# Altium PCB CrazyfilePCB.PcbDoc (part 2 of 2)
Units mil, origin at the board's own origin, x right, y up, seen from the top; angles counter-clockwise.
Board outline 3667.19 x 3670.52 mil, 4 copper layers (Top Layer, GND, VCC, Bottom Layer); 99 components, 96 nets, 358 pads, 80 vias.
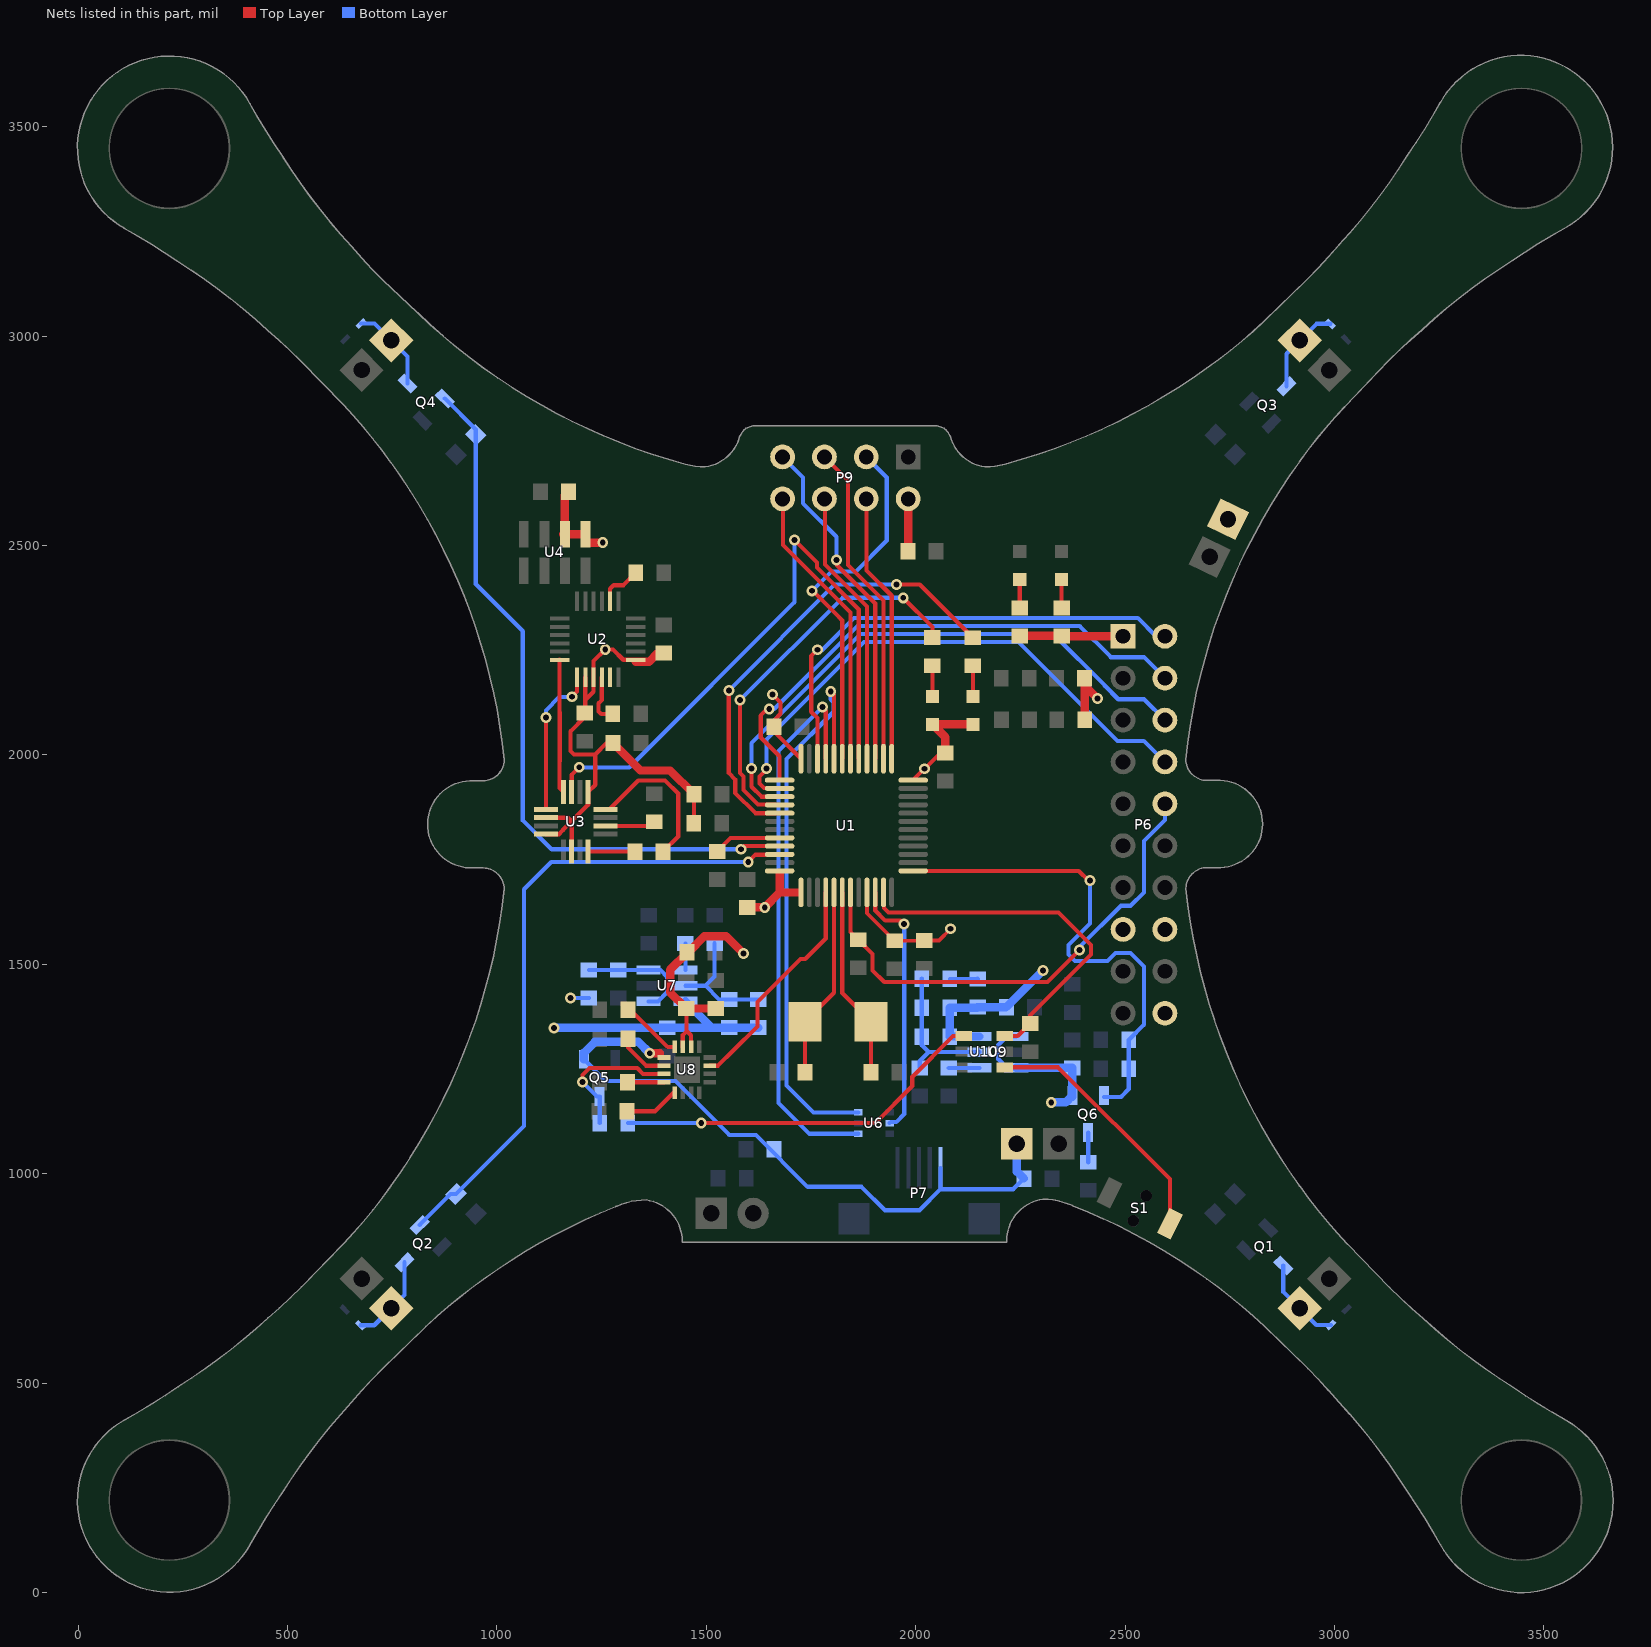
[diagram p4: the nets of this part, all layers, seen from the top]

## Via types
v1: diameter 25.98, hole 14, Top Layer to Bottom Layer, tented both sides, 77 vias
v2: diameter 152.84, hole 113.47, Top Layer to Bottom Layer, 2 vias
v3: diameter 25.98, hole 12.99, Top Layer to Bottom Layer, tented top, 1 vias

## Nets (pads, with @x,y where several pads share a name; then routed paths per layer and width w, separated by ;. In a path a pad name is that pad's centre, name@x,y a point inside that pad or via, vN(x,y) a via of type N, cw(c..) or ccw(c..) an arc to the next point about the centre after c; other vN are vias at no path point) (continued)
MOTOR3: Q2.2 R7.2 U1.46 | length 1556.2
  Top Layer w10: v1(1600.39,1744.09) 1617.97,1761.67 U1.46@1674.49,1761.67
  Bottom Layer w10: Q2.2@815.73,877.51 889.51,951.29 R7.2@902.47,951.29 1064.96,1113.78 1064.96,1679.13 1129.92,1744.09 v1(1600.39,1744.09)
MOTOR4: Q4.2 R9.2 U1.45 | length 1729.4
  Top Layer w10: v1(1582.68,1774.61) 1590.11,1782.04 U1.45@1675.17,1782.04
  Bottom Layer w10: Q4.2@875.81,2850.97 949.65,2777.13 R9.2@949.65,2764.44 949.65,2407.63 1062.01,2295.28 1062.01,1843.5 1130.91,1774.61 v1(1582.68,1774.61)
NetC1_2: C1.2 U1.5 Y1.1 | length 458.4
  Top Layer w10: C1.2@1735.93,1242.08 Y1.1@1735.93,1362.83 1805.09,1431.99 U1.5@1805.09,1671.81
NetC2_2: C2.2 U1.6 Y1.2 | length 555.5
  Top Layer w10: U1.6@1824.78,1671.81 1824.78,1431.35 ; C2.2@1893.36,1241.73 Y1.2@1893.41,1362.83 ; 1824.78,1431.35 Y1.2@1893.41,1362.83 ; 1824.78,1431.35 Y1.2@1893.41,1362.83
NetC3_1: 
NetC9_1: C9.1 U3.12 | length 368.2
  Top Layer w10: U3.12@1259.8,1869.58 1268.47,1869.58 1337.67,1938.78 1401.66,1938.78 1433.07,1907.37 1433.07,1805.16 C9.1@1396.94,1769.03
NetC9_2: C9.2 U3.8 | length 111.9
  Top Layer w10: U3.8@1218.07,1769.03 C9.2@1330.01,1769.03
NetC11_2: C11.2 U3.10 | length 120.5
  Top Layer w10: U3.10@1259.8,1830.21 1366.26,1830.21 C11.2@1376.18,1840.13
NetC13_2: C13.2 U2.10 | length 121
  Top Layer w10: U2.10@1250.66,2185.46 1250.66,2130.7 1243.05,2123.09 1243.05,2103.83 1249.17,2097.71 C13.2@1276.7,2097.71
NetC14_2: C14.2 U2.20 | length 106.8
  Top Layer w10: U2.20@1270.35,2366.88 1270.51,2367.04 1270.51,2396.59 1279.12,2405.2 1302.11,2405.2 C14.2@1331.73,2434.82
NetC28_2: C28.2 R22.1 U7.1 U7.3 | length 283.6
  Bottom Layer w10: R22.1@1220.06,1486.22 U7.3@1362.37,1486.22 1390.52,1486.22 1406.88,1469.86 1406.88,1433.52 1384.77,1411.42 U7.1@1362.37,1411.42
NetC30_2: C30.2 U7.4 | length 63.8
  Bottom Layer w10: C30.2@1450.18,1549.91 1450.18,1486.41 U7.4@1450.37,1486.22
NetC31_1: C31.1 R24.2 R25.1 U7.5 | length 298.1
  Bottom Layer w10: U7.5@1450.37,1448.82 1497.8,1448.82 ; R24.2@1520,1549.95 1520,1471.02 1497.8,1448.82 ; R25.1@1624.4,1415.73 C31.1@1555.12,1415.73 1530.89,1415.73 1497.8,1448.82
NetC33_2: C33.2 U9.4 | length 72.9
  Bottom Layer w10: C33.2@2079.3,1252.6 U9.4@2152.22,1252.6
NetC34_1: C34.1 R27.2 R28.1 R29.1 U9.5 | length 419.3
  Bottom Layer w10: R27.2@2009.9,1252.2 2009.9,1268.57 2031.42,1290.09 ; R28.1@2014.51,1396.74 R29.1@2014.51,1465.84 ; U9.5@2152.31,1290.09 2031.42,1290.09 ; C34.1@2014.73,1327.43 2014.73,1306.77 2031.42,1290.09 ; C34.1@2014.73,1327.43 R28.1@2014.71,1396.54 C34.1@2014.73,1327.43
NetC36_2: C36.2 Q6.2 R35.2 U1.13 | length 1213.1
  Top Layer w10: U1.13@1994.07,1722.99 2389.49,1722.99 2412.68,1699.8 v1(2416.34,1699.8)
  Bottom Layer w10: v1(2416.34,1699.8) 2416.34,1597.23 2364.74,1545.63 2364.74,1523.27 2380.55,1507.46 2458.09,1507.46 2477.26,1526.63 2513.32,1526.63 2545.28,1494.67 2545.28,1355.67 C36.2@2508.83,1319.23 R35.2@2508.83,1249.93 2508.83,1201.75 2490.47,1183.38 ; Q6.2@2450.06,1183.07 2491.14,1183.07
NetD1_2: D1.2 R4.2 | length 73.2
  Top Layer w10: D1.2@2136.81,2139.42 R4.2@2136.81,2212.6
NetD2_2: D2.2 R5.2 | length 73.3
  Top Layer w10: D2.2@2040.19,2139.67 R5.2@2040.19,2212.95
NetD3_1: D3.1 R31.1 | length 68.4
  Top Layer w10: R31.1@2348.23,2350.59 D3.1@2348.23,2419.03
NetD4_1: D4.1 R32.1 | length 67.9
  Top Layer w10: R32.1@2248.58,2351.01 D4.1@2248.58,2418.89
NetH1_1: H1.1 P1.1 Q1.1 | length 209.5
  Bottom Layer w10: Q1.1@2878.01,780.88 2878.01,717.46 P1.1@2917.09,678.39 2956.64,638.83 H1.1@2991.53,638.83
NetH2_1: H2.1 P2.2 Q2.1 | length 213.3
  Bottom Layer w10: H2.1@674.27,637.93 707.13,637.93 P2.2@747.9,678.7 779.68,710.48 Q2.1@779.68,788.29
NetH3_1: H3.1 P3.2 Q3.1 | length 212.1
  Bottom Layer w10: Q3.1@2885.72,2880.01 2885.72,2957.92 P3.2@2917.4,2989.6 2957.07,3029.27 H3.1@2990.33,3029.27
NetH4_1: H4.1 P4.1 Q4.1 | length 207.6
  Bottom Layer w10: H4.1@675.57,3029.87 707.65,3029.87 P4.1@747.81,2989.71 786.59,2950.94 Q4.1@786.59,2887.02
NetP9_3: 
NetP9_4: 
NetP9_5: 
NetP9_6: 
NetP9_7: 
NetP9_8: 
NetQ5_3: Q5.3 R20.2 U8.15 | length 342.6
  Top Layer w10: v1(1204.72,1218.5) 1204.72,1235.68 1221.25,1252.2 1335.21,1252.2 1349.33,1238.09 U8.15@1399.21,1238.09
  Bottom Layer w10: v1(1204.72,1218.5) 1238.7,1184.53 Q5.3@1245.27,1184.53 ; R20.2@1245.54,1120.64 Q5.3@1245.54,1184.26
NetQ6_3: Q6.3 R33.1 | length 70.4
  Bottom Layer w10: R33.1@2411.98,1027.34 Q6.3@2411.98,1097.75
NetR1_2: R1.2 U1.44 | length 162.6
  Top Layer w10: R1.2@1525.92,1769.48 1558.17,1801.73 U1.44@1675.17,1801.73
NetR4_1: R4.1 U1.41 | length 1117.3
  Top Layer w10: v1(1553.96,2153.92) 1553.96,1956.46 1569.08,1941.34 1569.08,1909.02 1617.32,1860.78 U1.41@1675.17,1860.78 ; v1(1954.72,2406.5) 2009.84,2406.5 R4.1@2136.81,2279.53
  Bottom Layer w10: v1(1553.96,2153.92) 1806.53,2406.5 v1(1954.72,2406.5)
NetR5_1: R5.1 U1.40 | length 933.8
  Top Layer w10: v1(1580.95,2130.93) 1580.95,1956.34 1588.94,1948.35 1588.94,1916.03 1623.82,1881.15 1674.49,1881.15 U1.40@1675.17,1880.47 ; v1(1970.47,2375) 2040.19,2305.28 R5.1@2040.19,2279.88
  Bottom Layer w10: v1(1580.95,2130.93) 1825.02,2375 v1(1970.47,2375)
NetR15_2: 
NetR16_2: R16.2 U8.12 | length 148.3
  Top Layer w10: R16.2@1312.81,1391.2 1319.41,1391.2 1407.95,1302.65 U8.12@1424.41,1302.65
NetR17_2: R17.2 U8.14 | length 124.6
  Top Layer w10: R17.2@1312.81,1321.6 1312.81,1301.48 1356.51,1257.77 U8.14@1399.21,1257.77
NetR18_2: R18.2 U8.16 | length 87.4
  Top Layer w10: R18.2@1311.81,1218.4 U8.16@1399.21,1218.4
NetR19_2: R19.2 U8.1 | length 129.4
  Top Layer w10: R19.2@1311.11,1148.88 1377.85,1148.88 U8.1@1422.18,1193.21
NetR20_1: R20.1 U10.4 | length 900.3
  Top Layer w10: v1(1488.19,1121.06) 1903.74,1121.06 1992,1209.32 1992,1231.18 2089.52,1328.7 U10.4@2114.4,1328.7
  Bottom Layer w10: R20.1@1312.89,1121.06 v1(1488.19,1121.06)
NetR29_2: R29.2 R30.1 | length 67.8
  Bottom Layer w10: R29.2@2082.11,1464.57 R30.1@2148.62,1464.57 ; R30.1@2147.96,1465.84 R30.1@2148.88,1464.92
NetS1_2: S1.2 U10.1 | length 611.2
  Top Layer w10: U10.1@2212.83,1253.89 2340.3,1253.89 2607.27,986.93 S1.2@2607.27,880.76
NetU1_13: 
NetU2_6: U2.6 U3.16 | length 319.4
  Top Layer w10: U2.6@1149.71,2226.95 1149.71,2101.37 1150.02,2101.06 1150.02,1984.67 1149.71,1984.36 1149.71,1921.01 U3.16@1159.01,1911.71
NetU2_7: U2.7 U3.1 | length 368.3
  Top Layer w10: U3.1@1117.28,1869.58 v1@1117.28,2089.41 ; v1@1180.12,2138.88 1180.12,2137.8 1179.25,2138.67 v1(1179.25,2138.88) 1191.61,2151.24 U2.7@1191.61,2185.46
  Bottom Layer w10: v1(1117.13,2089.57) 1117.13,2106.3 1148.62,2137.79 1180.12,2137.79 1179.25,2138.67 v1(1179.25,2138.88)
NetU2_11: U2.11
NetU2_12: 
NetU2_23: 
NetU2_24: 
NetU3_15: 
NetU6_1: 
NetU8_5: 
NetU8_6: 
NetU8_9: 
PGOOD: U1.4 U8.7 | length 546.8
  Top Layer w10: U8.7@1508.66,1257.77 1528.23,1257.77 1564.39,1293.94 1622.05,1351.59 1622.05,1409.7 1725.01,1512.66 1736.31,1512.66 1785.41,1561.76 U1.4@1785.41,1671.81
SNRST: C3.1 P6.10 U1.7 | length 1186.1
  Top Layer w10: U1.7@1844.46,1671.81 1844.46,1577.12 C3.1@1863.08,1558.5 1897.34,1524.25 1897.34,1485.2 1925.08,1457.46 2314.74,1457.46 v1(2391.73,1534.45)
  Bottom Layer w10: v1@2391.73,1541.1 2490.21,1639.57 2513.32,1639.57 2545.28,1671.53 2545.28,1794.64 2595.29,1844.66 P6.10@2595.29,1883.1
SPI_MISO: P9.7 U1.27 | length 812.3
  Top Layer w10: v1(1811.02,2465.55) 1811.02,2454.04 1903.52,2361.54 U1.27@1903.52,1990.7
  Bottom Layer w10: P9.7@1682.2,2711.3 1731.3,2662.2 1731.3,2600.64 1811.02,2520.92 v1(1811.02,2465.55)
SPI_MOSI: P9.6 U1.28 | length 660.9
  Top Layer w10: P9.6@1783.46,2610.04 1783.46,2454.72 1883.83,2354.35 U1.28@1883.83,1990.7
SPI_SCK: P9.5 U1.26 | length 779
  Top Layer w10: P9.5@1782.2,2711.3 1838.67,2654.83 1838.67,2453.26 1923.2,2368.72 U1.26@1923.2,1990.7
SYSOFF: R15.2 U1.11 U10.3 | length 889.6
  Top Layer w10: U1.11@1923.2,1671.81 1924.19,1670.83 1924.19,1634.53 1935.14,1623.57 2340.89,1623.57 2405.46,1559 2405.46,1558.89 2418.72,1545.63 2418.72,1523.27 2273.43,1377.97 R15.2@2273.43,1358.15 2243.97,1328.7 U10.3@2212.83,1328.7
TCK: P6.4 U1.37 | length 1272.7
  Top Layer w9: U1.37@1675.17,1939.52 1675.17,1996.04
  Top Layer w10: v1@1645.67,2109.25 1629.94,2093.52 1629.94,2042 1675.17,1996.77
  Bottom Layer w10: v1(1650.59,2109.25) 1662.48,2109.25 1860.86,2307.63 2391.73,2307.63 2466.09,2233.27 2545.12,2233.27 P6.4@2595.29,2183.1
TDI: P6.8 U1.38 | length 1329.4
  Top Layer w10: v1@1643.7,1965.11 1626.94,1948.35 1626.94,1931.77 1637.9,1920.82 1674.19,1920.82 U1.38@1675.17,1919.84
  Bottom Layer w10: v1(1643.7,1967.52) 1643.7,2036.73 1876.6,2269.63 2246.06,2269.63 2482.23,2033.46 2544.93,2033.46 P6.8@2595.29,1983.1
TDO: P6.6 U1.39 | length 1422
  Top Layer w10: v1(1607.94,1967.52) 1607.94,1923.9 1631.69,1900.15 U1.39@1675.17,1900.15
  Bottom Layer w10: P6.6@2595.29,2083.1 2545.52,2132.87 2483.96,2132.87 2451.76,2165.07 2451.76,2165.36 2328.5,2288.63 1868.73,2288.63 1607.96,2027.86 ; 1607.96,2027.86 1607.96,1967.52 1607.96,2027.86
TMS: P6.2 U1.34 | length 1151.8
  Top Layer w10: U1.34@1765.72,1990.7 1765.72,2087.84 1750.57,2102.99 1750.57,2235.8 v1(1765.75,2250.98)
  Bottom Layer w10: v1(1765.75,2250.98) 1777.35,2250.98 1852.99,2326.63 2530.62,2326.63 2574.14,2283.1 P6.2@2595.29,2283.1
USB_CON: U1.10 U6.5 | length 623.4
  Top Layer w10: U1.10@1903.52,1671.81 1903.52,1628.33 1927.27,1604.57 1964.32,1604.57 v1(1972.44,1596.46)
  Bottom Layer w10: U6.5@1937.93,1120.68 1940.85,1123.6 1953.9,1123.6 1972.74,1142.43 v1@1972.74,1596.46
USBD+: U1.33 U6.1 | length 1336.4
  Top Layer w10: v1(1777.56,2114.17) 1785.41,2106.32 U1.33@1785.41,1990.7
  Bottom Layer w10: v1(1777.56,2114.17) 1672.78,2009.39 1672.78,1168.84 1746.54,1095.09 U6.1@1863.13,1095.09
USBD-: U1.32 U6.3 | length 1352.8
  Top Layer w10: v1(1797.24,2151.57) 1805.09,2143.72 U1.32@1805.09,1990.7
  Bottom Layer w10: v1(1797.24,2151.57) 1797.24,2132.66 1804.55,2125.35 1804.55,2102.99 1691.78,1990.22 1691.78,1210.63 1756.14,1146.27 U6.3@1863.13,1146.27
VCC: C4.2 C5.1 C6.2 C18.2 C34.2 C35.1 D1.1 D2.1 P5.1 P6.1 P6.15 P9.2 R10.1 R11.1 R28.2 R30.2 R31.2 R32.2 U1.1 U1.24 U1.36 U1.48 U9.6 | length 1592.7
  Top Layer w10: v1(1658.46,2143.7) 1677.58,2124.58 1677.58,2098.07 1661.66,2082.15 C5.1@1661.66,2067.48 1661.66,2055.4 U1.36@1726.35,1990.7 U1.36@1726.35,2002.3 ; U1.24@1994.07,1939.82 2058.97,2004.72 C4.2@2070.78,2004.72
  Top Layer w20: C6.2@1597.45,1635.77 v1(1639.71,1635.77) 1675.2,1671.26 ; U1.48@1675.2,1718.65 1675.2,1671.26 ; U1.1@1721.49,1671.26 1675.2,1671.26 ; C18.2@1982.04,2486.08 P9.2@1982.04,2611.14 ; C4.2@2070.78,2004.72 2070.78,2042.16 D2.1@2040.19,2072.74 D1.1@2136.27,2072.74 ; R32.2@2248.58,2284.08 R31.2@2347.81,2284.08 ; R31.2@2348.43,2283.47 P6.1@2494.92,2283.47 ; R11.1@2403.54,2083.72 R10.1@2403.54,2165.35 ; R10.1@2403.54,2183.05 R10.1@2403.54,2165.35 ; v1(2434.06,2134.84) R10.1@2403.54,2165.35 ; P6.15@2487.8,1583.1 P6.15@2495.29,1583.1
  Bottom Layer w20: R28.2@2081.66,1396.52 C34.2@2081.66,1327.43 2152.25,1327.43 U9.6@2152.31,1327.49 ; R28.2@2081.64,1396.54 2147.43,1396.54 R30.2@2148.88,1397.99 R30.2@2149.02,1397.86 ; R30.2@2147.85,1397.64 R30.2@2148.88,1397.64 ; R30.2@2148.53,1397.64 R30.2@2148.88,1397.64 ; C35.1@2215.55,1397.64 R30.2@2148.88,1397.64 ; C35.1@2216.71,1397.86 v1(2304.13,1485.24)
  other v1: 2021.19,1966.94
VCCA: C7.2 C8.1 C10.2 C12.1 C15.2 C16.2 C31.2 C32.2 P6.20 R2.2 R3.2 R25.2 U1.9 U2.8 U2.9 U2.13 U3.2 U3.4 U3.6 U3.13 U4.1 U4.2 U7.6 | length 2337
  Top Layer w9: U1.9@1883.83,1671.81 1883.83,1621.85 C7.2@1949.58,1556.1 ; C7.2@1950.56,1556.1 C8.1@2019.69,1556.1 ; C8.1@2020.11,1556.53 2055.54,1556.53 v1(2083.66,1584.65)
  Top Layer w10: U3.4@1117.28,1810.53 1148.17,1810.53 1157.22,1819.59 1157.22,1819.98 1178.7,1841.45 ; U3.2@1117.28,1849.9 1170.25,1849.9 1178.7,1841.45 ; 1178.7,1798.78 1178.7,1799.68 1178.7,1841.45 ; U2.8@1211.13,2185.3 1211.13,2130.91 ; C10.2@1262.26,2028.33 1234.85,2000.93 ; U2.13@1331.37,2227.12 1301.82,2227.12 1277.43,2251.5 v1(1258.86,2251.5) 1231.14,2223.78 1231.14,2185.62 U2.9@1230.98,2185.46 1230.98,2150.75 1211.13,2130.91 ; R3.2@1470.44,1837.02 R2.2@1470.44,1906.15 ; 1178.7,1841.45 1218.07,1880.82 U3.13@1218.07,1911.71 1234.85,1928.5 1234.85,2000.93 ; 1211.13,2130.91 1211.13,2101.33 C15.2@1209.37,2099.57 1209.37,2089.85 1175.68,2056.16 1175.68,2009.13 1183.89,2000.93 1234.85,2000.93
  Top Layer w20: U4.2@1158.59,2526.61 U4.1@1207.8,2526.61 ; U4.2@1162.53,2526.61 1162.53,2619.28 C16.2@1171.35,2628.11 ; U4.1@1211.74,2506.93 v1(1252.92,2506.93) ; C10.2@1276.97,2028.33 C10.2@1279.44,2025.86 ; 1331.53,2222.12 1363.31,2222.12 1384.03,2242.84 C12.1@1399.01,2242.84 ; 1411.78,1962.6 1411.6,1962.78 ; R2.2@1470.44,1906.15 1413.82,1962.78 1411.6,1962.78 ; C10.2@1279.44,2025.47 C10.2@1279.44,2025.86 ; C10.2@1279.44,2025.47 1276.78,2028.14 1276.7,2028.21 C10.2@1279.44,2025.47 ; C10.2@1279.44,2025.86 1342.52,1962.78 1411.6,1962.78
  Bottom Layer w20: v1(1136.59,1348.2) C32.2@1407.41,1348.2 1513.59,1348.2 ; U7.6@1450.37,1411.42 1513.59,1348.2 ; C31.2@1554.52,1348.2 1513.59,1348.2 ; C31.2@1555.12,1348.8 R25.2@1624.4,1348.8
VCOM: C26.2 C27.2 C29.2 P6.16 Q6.1 R22.2 R34.2 U8.10 U8.11 U9.1 U9.3 | length 980.8
  Top Layer w10: U8.11@1444.09,1302.65 1444.09,1331.14 1452.52,1339.57 C27.2@1452.52,1394.29 ; 1454.72,1339.57 1463.78,1330.52 U8.10@1463.78,1302.65
  Top Layer w20: C27.2@1452.52,1394.29 1413.83,1432.98 1413.83,1486.81 R34.2@1454.87,1527.84 ; C27.2@1452.63,1394.19 C26.2@1522.47,1394.19 ; R34.2@1454.35,1528.36 1457.01,1528.36 1495.7,1567.04 1547.13,1567.04 v1(1588.58,1525.59)
  Bottom Layer w10: v1(1176.25,1419.22) R22.2@1219.99,1419.22 ; U9.3@2240.31,1252.69 2217.91,1252.69 2197.31,1273.29 2197.31,1306.89 2217.91,1327.49 U9.1@2240.31,1327.49 ; 2336.23,1252.69 2336.46,1252.46
  Bottom Layer w20: U9.3@2240.31,1252.69 2336.23,1252.46 2336.46,1252.46 ; v1(2323.82,1170.28) 2358.52,1170.28 Q6.1@2374.37,1186.12 ; 2336.23,1252.69 C29.2@2374.05,1252.69 ; C29.2@2374.37,1252.37 2374.37,1186.33 Q6.1@2374.37,1186.12 ; Q6.1@2374.58,1183.38 2374.37,1183.59 Q6.1@2374.37,1186.12 ; Q6.1@2374.58,1186.33 Q6.1@2374.37,1186.12
VUSB: C25.1 P7.1 P8.2 Q5.1 R21.2 U8.13 | length 1604.9
  Top Layer w10: 1389.26,1287.4 U8.13@1399.21,1277.46
  Top Layer w20: v1(1365.16,1287.4) 1389.26,1287.4
  Bottom Layer w10: Q5.1@1207.87,1273.11 1259.82,1221.16 1426.26,1221.16 1555.12,1092.3 1618.45,1092.3 1742.25,968.5 1870.74,968.5 1926.66,912.59 2009.07,912.59 2059.38,962.9 ; P7.1@2059.38,1013.8 2059.38,962.9 ; C25.1@2258.46,988.26 2233.1,962.9 2059.38,962.9
  Bottom Layer w20: Q5.1@1207.87,1273.11 1207.87,1288.58 1234.04,1314.75 1337.81,1314.75 v1(1365.16,1287.4) ; P8.2@2241.83,1070.97 2241.83,1004.89 C25.1@2258.46,988.26
W_CE: P9.3 U1.31 | length 878.7
  Top Layer w10: v1@1753.45,2392.22 1816.93,2328.74 1824.78,2320.89 U1.31@1824.78,1990.7
  Bottom Layer w10: v1(1752.95,2391.73) 1799.21,2437.99 1857.28,2437.99 1931.1,2511.81 1931.1,2662.4 P9.3@1882.2,2711.3
W_CK: U1.29 U3.15 | length 1477.3
  Top Layer w10: U3.15@1178.7,1911.71 1178.7,1952.32 v1(1196.85,1970.47) ; v1(1710.63,2512.8) 1764.13,2459.29 1764.13,2447.18 1864.15,2347.17 U1.29@1864.15,1990.7
  Bottom Layer w10: v1@1196.85,1970.13 1316.17,1970.13 1710.63,2364.58 v1(1710.63,2512.8)
W_CS: P9.4 U1.25 | length 644.8
  Top Layer w10: P9.4@1882.87,2610.63 1882.87,2439.96 1942.89,2379.94 U1.25@1942.89,1990.7
W_INT: P9.8 U1.30 | length 686
  Top Layer w10: P9.8@1683.46,2610.04 1683.46,2500.98 1844.46,2339.98 U1.30@1844.46,1990.7
pads on no net: P6.7 P7. P7.4 S1.0 U2.2 U2.3 U2.4 U2.5 U2.14 U2.15 U2.16 U2.17 U2.19 U2.21 U2.22 U3.3 U3.5 U3.7 U3.14 U4.6 U10.5
copper on no net: | length 4
  Top Layer w0.1: 218.07,3448.31 218.46,3448.31 ; 705.8,822.9 705.9,822.9 ; 3446.05,220.33 3446.44,220.33 ; 218.07,220.35 218.86,220.35 218.07,220.35
  Bottom Layer w0.1: 218.07,220.35 218.86,220.35 ; 218.07,3448.31 218.46,3448.31 218.07,3448.31
  other v2: 938.54,1834.13 2724.37,1834.92

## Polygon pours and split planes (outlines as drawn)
AGND on Top Layer "AGND" (solid, pour order 1000): 1031.5,2669.29 1032.48,2668.31 1205.71,2668.31 1443.9,2430.12 1444.88,2429.13 1444.88,1668.31 1202.76,1668.31 1079.72,1791.34 1079.72,2157.48 1079.72,2352.36 1034.45,2397.64 1031.5,2400.59 1031.5,2669.29
AGND on Bottom Layer "AGND" (solid, pour order 1001): 1033.46,2665.35 1211.61,2665.35 1405.51,2471.46 1405.51,2470.47 1446.85,2429.13 1446.85,1671.26 1204.72,1671.26 1085.63,1790.35 1085.63,2350.39 1036.42,2399.61 1033.46,2402.56 1033.46,2665.35
GND on GND (split plane): 1268 vertices, not listed, extent 18.44,19.54 3645.63,3650.3
DGND on GND (split plane): 181 vertices, not listed, extent 1501.47,1011.89 2766.66,2895.89
AGND on GND (split plane): 988.49,2885 1017.14,2865.86 1046.23,2847.38 1075.75,2829.57 1105.66,2812.45 1135.96,2796.03 1166.63,2780.31 1197.66,2765.31 1229.03,2751.03 1260.71,2737.47 1292.7,2724.65 1324.98,2712.57 1357.53,2701.24 1390.34,2690.67 1423.38,2680.85 1443.49,2675.38 1444.3,2675.07 1444.33,2675.06 1445.07,2674.93 1445.76,2674.72 1445.93,2674.7 1451.63,2673.11 1462.82,2670.71 1474.15,2668.99 1485.55,2667.95 1493.45,2667.71 1493.45,1904.12 1493.75,1902.58 1494.62,1901.28 1696.09,1699.8 1695,1698.7 1694.13,1697.4 1693.82,1695.87 1693.82,1424.21 1694.13,1422.68 1695,1421.37 1696.3,1420.5 1697.83,1420.2 2048.23,1420.2 2049.76,1420.5 2051.07,1421.37 2051.94,1422.68 2052.24,1424.21 2052.24,1562.91 2119.02,1562.91 2119.02,1426.76 2118.34,1425.75 2118.03,1424.21 2118.34,1422.68 2119.21,1421.37 2120.51,1420.5 2122.05,1420.2 2542.25,1420.2 2542.25,1352.06 2511.13,1320.94 2395.36,1320.94 2348.31,1368 2347.01,1368.87 2345.47,1369.17 2296.26,1369.17 2294.72,1368.87 2293.42,1368 2257.5,1332.07 2256.63,1330.77 2256.32,1329.23 2256.32,1285.62 2178.46,1207.75 1701.77,1207.75 1700.24,1207.45 1698.93,1206.58 1696.17,1203.82 1604.41,1203.82 1604.41,1211.61 1604.1,1213.15 1603.23,1214.45 1594.57,1223.12 1594.57,1273.93 1610.12,1289.48 1610.99,1290.79 1611.3,1292.32 1611.3,1600.39 1610.99,1601.93 1610.12,1603.23 1608.82,1604.1 1607.28,1604.41 1103.42,1604.41 1103.42,2201.77 1103.12,2203.31 1102.25,2204.61 1005,2301.86 1005,2865.38 1004.69,2866.92 1003.82,2868.22 983.63,2888.42
AGND on GND (split plane): 2381.65,942.62 2381.71,942.59 2381.43,942.67 2381.29,942.73
AGND on GND (split plane): 465.64,3028.9 465.63,3028.9 465.33,3029.15 465.29,3029.19
AGND on GND (split plane): 250.06,474.27 250.04,474.26 250.02,474.24 250,474.23 249.99,474.24 250.04,474.26 250.05,474.27 250.08,474.29
AGND on GND (split plane): 471.99,250.76 471.98,250.75 471.95,250.7 471.95,250.71 471.96,250.72 471.98,250.75 471.99,250.77 472,250.78
AGND on GND (split plane): 472.37,3417.13 472.38,3417.11 472.4,3417.09 472.38,3417.11 472.37,3417.13 472.35,3417.15 472.34,3417.17 472.35,3417.17
AGND on GND (split plane): 3412.92,3196.39 3412.88,3196.37 3412.86,3196.36 3412.84,3196.34 3412.85,3196.36 3412.88,3196.37 3412.9,3196.39 3412.92,3196.4
AGND on GND (split plane): 3190.96,3419.92 3190.95,3419.91 3190.94,3419.88 3190.96,3419.93
AGND on GND (split plane): 3191.74,251.12 3191.75,251.1 3191.72,251.14
AGND on GND (split plane): 3415.28,473.06 3415.28,473.05 3415.26,473.06 3415.24,473.08
AGND on GND (split plane): 248.83,3195.21 248.86,3195.19 248.81,3195.21 248.82,3195.22
AGND on GND (split plane): 3191.71,251.16 3191.72,251.14 3191.71,251.16 3191.7,251.18
AGND on GND (split plane): 3415.22,473.09 3415.24,473.08 3415.22,473.09 3415.2,473.11
AGND on GND (split plane): 3190.92,3419.86 3190.91,3419.85 3190.92,3419.87 3190.94,3419.88
AGND on GND (split plane): 248.88,3195.18 248.89,3195.16 248.87,3195.17 248.86,3195.19
AGND on GND (split plane): 762.65,2710.5 761.27,2712.19
AGND on GND (split plane): 2299.96,958.47 2299.96,958.48 2299.98,958.48
AGND on GND (split plane): 1038.03,1986.49 1037.97,1985.83 1038.03,1986.49
AGND on GND (split plane): 2624.95,1986.61 2624.88,1987.28
AGND on GND (split plane): 2304.55,958.82 2304.34,958.84
AGND on GND (split plane): 3270.22,3547.37 3270,3546.97 3269.11,3545.88 3270,3546.97 3270.22,3547.37
GND on GND (split plane): 392.7,123.26 392.91,123.66
AGND on GND (split plane): 3542.72,393.8 3542.32,394.01
AGND on GND (split plane): 2706.22,2906.46 2706.21,2906.44 2706.22,2906.46
VCCA on VCC (split plane): 925 vertices, not listed, extent 18.44,19.54 3645.63,3648.72
VCC on VCC (split plane): 470 vertices, not listed, extent 1453.18,1416.42 3644.45,3650.3
VCOM on VCC (split plane): 2631.55,1628.16 2636.72,1593.98 2639.25,1579.5 2639.25,1549.46 2632.2,1542.4 2570.87,1542.4 2569.33,1542.09 2568.03,1541.22 2546.37,1519.57 2545.5,1518.27 2545.2,1516.73 2545.2,1345.17 2393.82,1193.78 2392.94,1192.48 2392.64,1190.94 2392.64,1142.79 2312.69,1142.79 2092.41,1363.07 2091.1,1363.94 2089.57,1364.25 1190.64,1364.25 1150.67,1404.22 1150.67,1406.5 1150.67,1444.88 1150.67,1459.57 1481.3,1459.57 1482.84,1459.87 1484.14,1460.74 1594.18,1570.79 1880.23,1570.79 1912.11,1538.9 1913.42,1538.03 1914.95,1537.73 2190.85,1537.73 2319.01,1409.56 2320.31,1408.69 2321.85,1408.39 2419.29,1408.39 2420.83,1408.69 2422.13,1409.56 2549.1,1536.53 2549.97,1537.83 2550.27,1539.37 2550.27,1624.92 2592.64,1624.92 2594.18,1625.23 2595.48,1626.1 2627.7,1658.32
VCCA on VCC (split plane): 2381.65,942.62 2381.71,942.59 2381.43,942.67 2381.29,942.73
VCCA on VCC (split plane): 465.64,3028.9 465.63,3028.9 465.33,3029.15 465.29,3029.19
VCCA on VCC (split plane): 250.06,474.27 250.04,474.26 250.02,474.24 250,474.23 249.99,474.24 250.04,474.26 250.05,474.27 250.08,474.29
VCCA on VCC (split plane): 472.37,3417.13 472.38,3417.11 472.4,3417.09 472.38,3417.11 472.37,3417.13 472.35,3417.15 472.34,3417.17 472.35,3417.17
VCCA on VCC (split plane): 3412.92,3196.39 3412.88,3196.37 3412.86,3196.36 3412.84,3196.34 3412.85,3196.36 3412.88,3196.37 3412.9,3196.39 3412.92,3196.4
VCCA on VCC (split plane): 471.99,250.76 471.98,250.75 471.95,250.7 471.95,250.71 471.96,250.72 471.98,250.75 471.99,250.77 472,250.78
VCCA on VCC (split plane): 3190.96,3419.92 3190.95,3419.91 3190.94,3419.88 3190.96,3419.93
VCCA on VCC (split plane): 3415.28,473.06 3415.28,473.05 3415.26,473.06 3415.24,473.08
VCCA on VCC (split plane): 3191.74,251.12 3191.75,251.1 3191.72,251.14
VCCA on VCC (split plane): 248.83,3195.21 248.86,3195.19 248.81,3195.21 248.82,3195.22
VCCA on VCC (split plane): 3191.71,251.16 3191.72,251.14 3191.71,251.16 3191.7,251.18
VCCA on VCC (split plane): 3190.92,3419.86 3190.91,3419.85 3190.92,3419.87 3190.94,3419.88
VCCA on VCC (split plane): 3415.22,473.09 3415.24,473.08 3415.22,473.09 3415.2,473.11
VCCA on VCC (split plane): 248.88,3195.18 248.89,3195.16 248.87,3195.17 248.86,3195.19
VCCA on VCC (split plane): 762.65,2710.5 761.27,2712.19
VCCA on VCC (split plane): 2299.96,958.47 2299.96,958.48 2299.98,958.48
VCCA on VCC (split plane): 1038.03,1986.49 1037.97,1985.83 1038.03,1986.49
VCCA on VCC (split plane): 2624.95,1986.61 2624.88,1987.28
VCCA on VCC (split plane): 2304.55,958.82 2304.34,958.84
VCCA on VCC (split plane): 3270.22,3547.37 3270,3546.97 3270.22,3547.37
VCCA on VCC (split plane): 392.7,123.26 392.91,123.66
VCCA on VCC (split plane): 3542.72,393.8 3542.32,394.01
VCCA on VCC (split plane): 2706.22,2906.46 2706.21,2906.44 2706.22,2906.46

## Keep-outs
Keep-Out Layer:
  lines w3.94: 112.27,3258.63 cw(c-609.88,1953.43) 238.8,3180.13 ; 112.77,3258.61 cw(c218.07,3449.09) 408.93,3553.72 ccw(c1714.13,4275.87) 487.43,3427.19 ; 238.81,3180.12 cw(c-531.14,1953.43) 453.36,3015.66 cw(c-452.4,1953.43) 533.72,2941.51 634.6,2837.73 cw(c-255.55,1992.8) 747.6,2699.89 ; 239.98,489.32 cw(c-608.7,1716.02) 113.45,410.82 ccw(c218.07,219.96) 408.56,114.66 ; 239.99,489.33 ccw(c-529.96,1716.02) 454.54,653.78 ccw(c-451.22,1716.02) 534.91,727.93 635.78,831.72 ccw(c-254.37,1676.65) 748.78,969.56 ; 408.54,114.15 cw(c1713.74,-607.99) 487.04,240.69 cw(c1713.74,-529.25) 651.5,455.25 cw(c1713.74,-450.51) 725.65,535.61 829.43,636.49 cw(c1674.37,-253.66) 967.28,749.48 cw(c1832.24,-448.94) 1283.4,923.34 ; 487.44,3427.17 ccw(c1714.13,4197.13) 651.89,3212.62 ccw(c1714.13,4118.39) 726.04,3132.26 809.53,3054.04 ; 747.95,2700.14 cw(c-450.83,1834.13) 1020.21,1986.03 ; 748.56,969.72 ccw(c-450.83,1834.13) 1019.64,1680.98 ; 809.52,3054.04 ccw(c1831.69,4115.93) 1449.17,2692.51 ccw(c1497,2857.2) 1497.6,2685.71 ccw(c1483.78,2786.65) 1582.39,2761 ; 934.36,1732.17 967.73,1732.05 cw(c966.22,1678.63) 1019.61,1680.98 ; 934.36,1732.18 cw(c938.54,1834.13) 935.14,1936.12 968.46,1936.1 ; 968.46,1936.13 ccw(c966.5,1989.65) 1020,1987.29 ; 1286.18,924.29 cw(c1356.01,767.66) 1356.61,939.15 cw(c1342.79,838.21) 1444.68,838.1 2215.48,838.1 ; 1582.67,2760.87 cw(c1628.31,2740.04) 1595.18,2777.72 ; 1595.27,2777.58 cw(c1617.68,2740.04) 1618.86,2783.74 1831.85,2783.74 ; 1831.06,2783.74 2044.06,2783.74 cw(c2045.24,2740.04) 2067.65,2777.58 ; 2067.73,2777.72 cw(c2034.61,2740.04) 2080.24,2760.87 ; 2080.52,2761 ccw(c2179.13,2786.65) 2165.31,2685.71 ccw(c2165.91,2857.2) 2213.75,2692.51 ccw(c1832.24,4117.99) 2695.56,2921.24 ; 2215.48,839.68 cw(c2317.36,839.78) 2303.55,940.73 ; 2304.34,940.73 cw(c2304.93,769.24) 2374.76,925.87 ; 2375.52,925.4 cw(c1832.24,-448.94) 2696.42,749.88 cw(c1989.33,-253.27) 2834.26,636.89 2938.05,536 cw(c1949.96,-450.12) 3012.2,455.65 cw(c1949.96,-528.86) 3176.65,241.09 cw(c1949.96,-607.6) 3255.16,114.55 ccw(c3446.02,219.17) 3551.32,409.66 ; 2642.7,1986.82 cw(c4113.74,1834.92) 2914.97,2700.93 ; 2642.91,1984.14 ccw(c2696.42,1986.5) 2694.45,1932.98 ; 2643.27,1681.77 ccw(c4113.74,1834.92) 2914.35,970.51 ; 2643.31,1681.77 cw(c2696.7,1679.41) 2695.18,1732.83 2728.56,1732.95 ccw(c2724.37,1834.92) 2727.77,1936.91 2694.45,1936.89 ; 2695.63,2921.15 ccw(c1988.54,3924.29) 2833.47,3034.14 ; 2833.48,3034.14 2937.27,3135.02 ccw(c1949.17,4121.14) 3011.41,3215.38 ccw(c1949.17,4199.88) 3175.87,3429.93 ccw(c1949.17,4278.62) 3254.38,3556.48 ; 2908.1,2692.08 cw(c3929.95,1971.8) 3023.2,2832.49 ; 2916.5,968.38 ccw(c3919.65,1675.47) 3029.49,830.54 3130.37,726.75 ccw(c4116.5,1714.84) 3210.73,652.6 ccw(c4195.24,1714.84) 3425.28,488.15 ccw(c4273.98,1714.84) 3551.83,409.64 ; 3023.75,2832.99 3128.01,2942.7 cw(c4114.13,1954.61) 3208.37,3016.85 cw(c4192.87,1954.61) 3422.92,3181.3 ; 3254.36,3555.97 cw(c3444.84,3450.67) 3549.47,3259.81 ccw(c4271.61,1954.61) 3422.93,3181.31

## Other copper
GND (plane layer: these items are gaps in the copper):
  lines w7.87: 810.9,3055.47 1000.98,2865.38 1000.98,2300.2 1099.41,2201.77 1099.41,1601.38 1100.39,1600.39 1607.28,1600.39 1607.28,1292.32 1590.55,1275.59 1590.55,1221.46 1600.39,1211.61 1600.39,1199.8 1697.83,1199.8 1701.77,1203.74 2180.12,1203.74 2260.33,1283.96 2260.33,1329.23 2296.26,1365.16 2345.47,1365.16 2393.7,1316.93 2458.66,1316.93 ; 1497.46,2687.69 1497.46,1904.12 1701.77,1699.8 1697.83,1695.87 1697.83,1424.21 2048.23,1424.21 2048.23,1566.93 2123.03,1566.93 2123.03,1425.2 2122.05,1424.21 2546.26,1424.21 2546.26,1350.39 2512.8,1316.93 2458.66,1316.93 ; 2695.04,2923.15 2695.04,2600.24 2695.2,2600.39 2768.7,2600.39 2770.67,2598.43 2770.67,2538.39 2725.39,2493.11 2725.39,2449.8 2695.87,2449.8 2546.26,2300.2 2546.26,1451.77 2546.26,1437.99 2657.48,1437.99 2656.5,1437.01 2656.5,1272.64 2391.73,1007.87 2263.78,1007.87 2261.81,1009.84 2261.81,1200.79 2311.02,1250 2457.68,1250 2458.66,1250.98 2458.66,1316.93
VCC (plane layer: these items are gaps in the copper):
  lines w7.87: 1449.17,2692.51 1449.17,2143.35 1449.17,1728.7 1495.71,1728.7 1617.13,1607.28 2024.61,1607.28 2042.32,1625 2054.13,1625 2109.25,1625 2115.65,1618.6 2148.62,1585.63 2321.85,1412.4 2419.29,1412.4 2546.26,1539.37 2546.26,1628.94 2592.64,1628.94 2645.28,1681.58 ; 2192.51,1541.74 2047.83,1541.74 1914.95,1541.74 1881.89,1574.8 1859.25,1574.8 1592.52,1574.8 1481.3,1463.58 1473.43,1463.58 1146.65,1463.58 ; 2643.27,1681.77 2643.27,1547.8 2633.86,1538.39 2570.87,1538.39 2549.21,1516.73 2549.21,1343.5 2396.65,1190.94 2396.65,1138.78 2311.02,1138.78 2089.57,1360.24 1188.98,1360.24 1146.65,1402.56 1146.65,1406.5 1146.65,1444.88 1146.65,1463.58 ; 1146.65,1463.58 1146.65,1463.58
